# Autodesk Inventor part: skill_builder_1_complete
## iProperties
Created: 2009-03
Part Number: skill_builder_1_complete
Document SubType Name: Modeling
Designer: PN
Density: 1 g/cm^3
Author: PN
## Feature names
1. Extrusion1
2. Shell1
3. Split1
4. Split2
5. Split3
6. Fillet1
7. Fillet2
